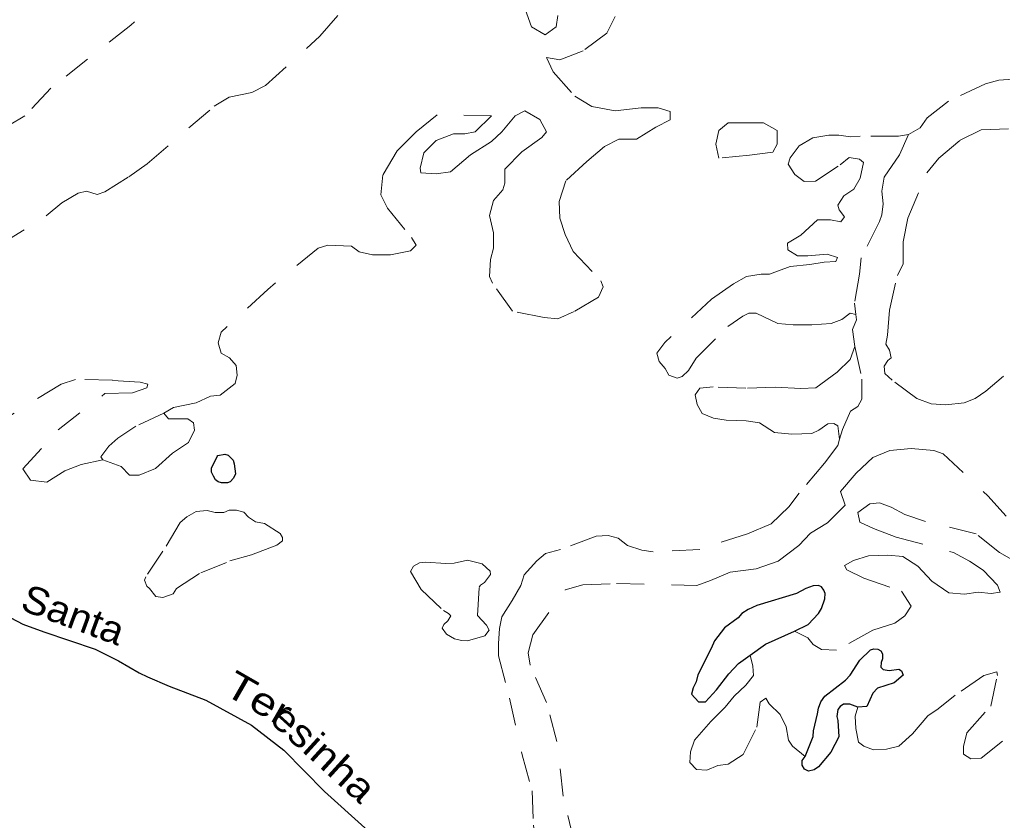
# Model space of a CAD drawing. Extents: x 344.9 to 371, y 7566.4 to 7594.3.
# Drawn here: x 362.086 to 365.656, y 7583.086 to 7585.996 of the extents above; entities that cross this region are included whole.
import ezdxf
from ezdxf.enums import TextEntityAlignment as Align

# ---------------------------------------------------------------- set-up
doc = ezdxf.new("R2010")
doc.units = 0
doc.header["$LTSCALE"] = 0.04
doc.linetypes.add('SHORT_DASHED', pattern=[2.7, 1.5, -1.2])
for name, color, linetype, lineweight in [('17', 7, 'SHORT_DASHED', 13), ('2', 7, 'Continuous', 25), ('21', 7, 'SHORT_DASHED', 13), ('7', 7, 'Continuous', 25)]:
    doc.layers.add(name, color=color, linetype=linetype, lineweight=lineweight)
doc.layers.add('61', color=7, linetype='Continuous')

msp = doc.modelspace()

# ---------------------------------------------------------------- linework, layer by layer
at = {"layer": '17'}
for points in [[(365.3151, 7585.5786), (365.282, 7585.5043), (365.227, 7585.4229), (365.2182, 7585.3723), (365.2226, 7585.3261), (365.2182, 7585.2865), (365.2094, 7585.2623), (365.1434, 7585.1303), (365.1368, 7585.0709), (365.1192, 7584.9653), (365.123, 7584.9245)], [(365.12, 7584.8076), (365.1456, 7584.6893), (365.1456, 7584.6167), (365.1302, 7584.5903), (365.1038, 7584.5727), (365.0752, 7584.5067), (365.0637, 7584.4714)], [(362.6098, 7584.5657), (362.5082, 7584.5184), (362.4428, 7584.4748), (362.4096, 7584.4454), (362.3802, 7584.4065), (362.3884, 7584.3962)]]:
    msp.add_lwpolyline(points, dxfattribs=at)
at = {"layer": '2'}
msp.add_lwpolyline([(362.8031, 7584.4079), (362.8063, 7584.4118), (362.8309, 7584.4166), (362.8428, 7584.4126), (362.8611, 7584.3952), (362.8656, 7584.382), (362.8698, 7584.3452), (362.8627, 7584.3293), (362.85, 7584.3158), (362.841, 7584.3126), (362.819, 7584.3121), (362.8065, 7584.3163), (362.7968, 7584.3237), (362.7894, 7584.3362), (362.7832, 7584.3507), (362.7824, 7584.3658)], close=True, dxfattribs=at)
for points in [[(364.9008, 7583.774), (364.9507, 7583.7976), (364.9882, 7583.8379), (364.9989, 7583.856), (365.0104, 7583.8908), (365.0118, 7583.9098), (365.0076, 7583.9223), (364.9988, 7583.9343), (364.9881, 7583.939), (364.9682, 7583.938), (364.9418, 7583.9283), (364.9076, 7583.9102), (364.764, 7583.8668), (364.7325, 7583.8524), (364.7089, 7583.8371), (364.6955, 7583.8222), (364.6462, 7583.7861), (364.6096, 7583.7385), (364.5985, 7583.7099), (364.5493, 7583.6146), (364.5437, 7583.5892), (364.5326, 7583.567), (364.5271, 7583.5447), (364.5517, 7583.5169), (364.5779, 7583.5169), (364.6168, 7583.5606), (364.6621, 7583.6185), (364.6978, 7583.6559), (364.7391, 7583.686)], [(364.7391, 7583.686), (364.7955, 7583.7257), (364.9008, 7583.774)], [(365.1385, 7583.6686), (365.1774, 7583.7059), (365.1894, 7583.7091), (365.2037, 7583.7083), (365.2139, 7583.7019), (365.2203, 7583.6916), (365.2203, 7583.6734), (365.2155, 7583.6591), (365.2147, 7583.6432), (365.2227, 7583.6336), (365.2449, 7583.6304), (365.2799, 7583.6352), (365.2894, 7583.6297), (365.2957, 7583.613), (365.2632, 7583.5852), (365.2021, 7583.5661), (365.1854, 7583.5487), (365.1631, 7583.4994), (365.1314, 7583.4978)], [(364.9844, 7583.4733), (364.9876, 7583.4939), (364.9964, 7583.5161), (365.0115, 7583.5368), (365.0861, 7583.5955), (365.1028, 7583.613), (365.1385, 7583.6686)], [(365.1314, 7583.4978), (365.102, 7583.5082), (365.079, 7583.5082), (365.0663, 7583.5002), (365.0583, 7583.4891), (365.0543, 7583.4637), (365.0583, 7583.4486), (365.0623, 7583.3899), (365.0329, 7583.3335), (364.9884, 7583.2803), (364.9718, 7583.2691), (364.9511, 7583.2652), (364.9368, 7583.2715), (364.9289, 7583.2866), (364.9289, 7583.3033), (364.94, 7583.3176)], [(364.94, 7583.3176), (364.9686, 7583.3907), (364.9701, 7583.4113), (364.9844, 7583.4733)]]:
    msp.add_lwpolyline(points, dxfattribs=at)
at = {"layer": '21'}
for points in [[(363.0764, 7586.6295), (363.067, 7586.6106), (363.067, 7586.5349), (363.0409, 7586.4829), (362.9771, 7586.4167), (362.944, 7586.3765), (362.7878, 7586.2629), (362.6553, 7586.1174), (362.4898, 7585.9755), (362.1988, 7585.7461), (362.1042, 7585.6456), (362.0474, 7585.6125)], [(362.0168, 7585.1797), (362.1824, 7585.2826), (362.2392, 7585.3299), (362.2983, 7585.3654), (362.329, 7585.3725), (362.3669, 7585.3606), (362.3953, 7585.3701), (362.4828, 7585.4245), (362.549, 7585.4718), (362.7926, 7585.6811), (362.847, 7585.7142), (362.9298, 7585.7308), (362.9795, 7585.7568), (363.1758, 7585.9354), (363.2846, 7586.0607)], [(363.916, 7586.0512), (363.9457, 7585.9701), (363.9944, 7585.9403), (364.035, 7585.9701), (364.0404, 7586.0106)], [(364.2487, 7586.0066), (364.219, 7585.9471), (364.1324, 7585.8822), (364.0485, 7585.8497), (363.9998, 7585.8578), (364.0242, 7585.8064), (364.1026, 7585.7171), (364.1648, 7585.6806), (364.2487, 7585.6644), (364.3434, 7585.6752), (364.4056, 7585.6752), (364.4489, 7585.6617), (364.4489, 7585.6319), (364.3975, 7585.6049), (364.3272, 7585.5616), (364.2622, 7585.5616), (364.2108, 7585.5345), (364.1459, 7585.4804), (364.0701, 7585.4101), (364.0458, 7585.3343), (364.0485, 7585.2748), (364.0674, 7585.2153), (364.0972, 7585.1531), (364.1973, 7585.0463), (364.2054, 7585.0247), (364.1892, 7584.9868), (364.0999, 7584.9354), (364.0404, 7584.9083), (363.9917, 7584.9138), (363.8758, 7584.9358), (363.8032, 7585.0378), (363.7928, 7585.062), (363.7962, 7585.1243), (363.8066, 7585.1658), (363.8066, 7585.2211), (363.7928, 7585.2834), (363.8066, 7585.3387), (363.8412, 7585.3768), (363.8481, 7585.401), (363.8481, 7585.4529), (363.9104, 7585.5151), (363.983, 7585.567), (364.0003, 7585.5878), (363.9761, 7585.6327), (363.9208, 7585.6639), (363.8862, 7585.6466), (363.8378, 7585.5878), (363.7997, 7585.5532), (363.7236, 7585.5048), (363.651, 7585.4425), (363.5991, 7585.4356), (363.5437, 7585.439), (363.5403, 7585.4563), (363.5541, 7585.5117), (363.5991, 7585.5566), (363.6613, 7585.5809), (363.7029, 7585.5809), (363.7409, 7585.5878), (363.7997, 7585.6466), (363.6025, 7585.65), (363.5265, 7585.5878), (363.4573, 7585.5186), (363.4054, 7585.4321), (363.3985, 7585.3595), (363.4227, 7585.3111), (363.5092, 7585.2039), (363.5265, 7585.1762), (363.5057, 7585.1554), (363.4331, 7585.1416), (363.3673, 7585.1416)], [(365.6937, 7585.7789), (365.6436, 7585.7759), (365.595, 7585.7622), (365.4599, 7585.6999), (365.3825, 7585.6392), (365.3576, 7585.6029), (365.3151, 7585.5786)], [(365.6605, 7584.6997), (365.5956, 7584.6453), (365.5574, 7584.6185), (365.5173, 7584.6033), (365.4504, 7584.5956), (365.397, 7584.5994), (365.3454, 7584.6185), (365.2556, 7584.6854), (365.2289, 7584.7102), (365.227, 7584.7369), (365.2401, 7584.7566), (365.2518, 7584.7665), (365.246, 7584.7952), (365.2327, 7584.8162), (365.2384, 7584.8487), (365.246, 7584.9403), (365.2747, 7585.0664), (365.2957, 7585.1084), (365.2957, 7585.1886), (365.3129, 7585.2746), (365.3817, 7585.4388), (365.4256, 7585.4923), (365.502, 7585.5572), (365.5784, 7585.5954), (365.6777, 7585.5993)], [(365.3151, 7585.5786), (365.2786, 7585.5726), (365.139, 7585.5726), (365.104, 7585.5695), (365.0615, 7585.5756), (365.0251, 7585.5756), (364.9674, 7585.5665), (364.9173, 7585.5376), (364.8854, 7585.4936), (364.8778, 7585.4708), (364.9021, 7585.4329), (364.9355, 7585.4071), (364.9765, 7585.4086), (365.0661, 7585.4678), (365.0995, 7585.4951), (365.1374, 7585.4891), (365.1511, 7585.4769), (365.139, 7585.4192), (365.1162, 7585.3798), (365.0798, 7585.3555), (365.0585, 7585.3213)], [(365.0585, 7585.3213), (365.063, 7585.3046), (365.0828, 7585.2788), (365.0691, 7585.2606), (365.0311, 7585.2682), (364.9841, 7585.2682), (364.9233, 7585.212), (364.8748, 7585.1831), (364.8763, 7585.1589), (364.9112, 7585.1376), (364.9492, 7585.1376), (365.019, 7585.1437), (365.0569, 7585.1315), (365.0509, 7585.1163), (365.0084, 7585.1148), (364.9567, 7585.1057), (364.8847, 7585.0984), (364.8103, 7585.0711), (364.7799, 7585.0711), (364.7268, 7585.062), (364.6797, 7585.0362), (364.5993, 7584.98), (364.4292, 7584.8221), (364.4004, 7584.7842), (364.4095, 7584.7538), (364.4307, 7584.728), (364.4444, 7584.7037), (364.4748, 7584.6931), (364.493, 7584.6991), (364.5158, 7584.7204), (364.5431, 7584.7659), (364.6585, 7584.8805), (364.7131, 7584.9185), (364.7344, 7584.9291), (364.7617, 7584.9291), (364.8406, 7584.8911), (364.8953, 7584.8866), (364.9636, 7584.8866), (365.0335, 7584.8911), (365.0729, 7584.9063), (365.1033, 7584.9291), (365.123, 7584.9245)], [(363.2048, 7585.1762), (363.1702, 7585.1658), (362.9868, 7585.0153), (362.8174, 7584.8597), (362.807, 7584.8216), (362.8174, 7584.7836), (362.8485, 7584.7663), (362.8727, 7584.7386), (362.8762, 7584.704), (362.8692, 7584.6729), (362.8139, 7584.6314), (362.7793, 7584.6279), (362.7274, 7584.6037), (362.6444, 7584.5864), (362.6098, 7584.5657)], [(363.3673, 7585.1416), (363.3189, 7585.152), (363.2912, 7585.1727), (363.2048, 7585.1762)], [(365.123, 7584.9245), (365.1261, 7584.9048), (365.1109, 7584.8699), (365.12, 7584.8076)], [(365.12, 7584.8076), (365.1033, 7584.7606), (365.0562, 7584.715), (364.9788, 7584.6581), (364.9241, 7584.6551), (364.83, 7584.6596), (364.7237, 7584.6566), (364.6053, 7584.6611), (364.5567, 7584.6566), (364.54, 7584.6323), (364.5476, 7584.5974), (364.5658, 7584.564), (364.6068, 7584.5473), (364.6524, 7584.5397), (364.7253, 7584.5382), (364.7738, 7584.5306), (364.8285, 7584.4957), (364.8908, 7584.4888), (364.9636, 7584.4919), (364.9894, 7584.504), (365.0213, 7584.5268), (365.0441, 7584.5283), (365.0578, 7584.5192), (365.0637, 7584.4714)], [(362.3884, 7584.3962), (362.3089, 7584.3789), (362.2501, 7584.3564), (362.1844, 7584.3149), (362.1256, 7584.3218), (362.0979, 7584.3633), (362.2259, 7584.5051), (362.3954, 7584.6366), (362.4957, 7584.64), (362.5476, 7584.6573), (362.551, 7584.6712), (362.5234, 7584.6781), (362.423, 7584.685), (362.2881, 7584.6885), (362.2363, 7584.6712), (361.9293, 7584.4819)], [(362.6098, 7584.5657), (362.6271, 7584.5449), (362.6963, 7584.5449), (362.717, 7584.5311), (362.7205, 7584.5034), (362.6997, 7584.4585), (362.6409, 7584.4204), (362.5787, 7584.3651), (362.5199, 7584.3409), (362.4853, 7584.3409), (362.4542, 7584.372), (362.3884, 7584.3962)], [(365.0637, 7584.4714), (365.0577, 7584.4486), (365.0091, 7584.3834), (364.918, 7584.2748), (364.8801, 7584.2247), (364.8163, 7584.164), (364.7298, 7584.1275), (364.5567, 7584.0706), (364.3867, 7584.0615), (364.3457, 7584.0675), (364.2941, 7584.0842), (364.2607, 7584.1116), (364.2242, 7584.1207), (364.1802, 7584.1192), (364.0512, 7584.0698), (363.9965, 7584.0561), (363.9646, 7584.0288), (363.9191, 7583.9787), (363.9069, 7583.9392), (363.875, 7583.8846)], [(364.1008, 7583.0057), (364.0607, 7583.1744), (364.0371, 7583.3724), (363.9994, 7583.5139), (363.9405, 7583.6496), (363.9334, 7583.6944), (363.9499, 7583.7604), (364.0678, 7583.9231), (364.1315, 7583.942), (364.2541, 7583.9467), (364.5465, 7583.9396), (364.596, 7583.9573), (364.6668, 7583.988), (364.7611, 7583.9998), (364.8413, 7584.0281), (364.9167, 7584.0847), (364.9592, 7584.1295), (365.0205, 7584.1672), (365.0842, 7584.2309), (365.0677, 7584.2816), (365.1243, 7584.3477), (365.1856, 7584.4043), (365.2469, 7584.4302), (365.3247, 7584.4373), (365.4073, 7584.4302), (365.4403, 7584.4184), (365.603, 7584.2651), (365.6808, 7584.1791)], [(365.7209, 7584.0164), (365.6454, 7584.0588), (365.5606, 7584.1272), (365.3766, 7584.172), (365.3012, 7584.1979), (365.2516, 7584.2239), (365.2092, 7584.2404), (365.1738, 7584.2357), (365.1314, 7584.205), (365.1384, 7584.1696), (365.188, 7584.1461), (365.2705, 7584.1154), (365.478, 7584.0588), (365.537, 7584.0282), (365.5865, 7583.9952), (365.6384, 7583.9409), (365.6478, 7583.915), (365.6148, 7583.9103), (365.5676, 7583.915), (365.5181, 7583.9079), (365.4615, 7583.9126), (365.4002, 7583.9551), (365.3483, 7584.0093), (365.2941, 7584.0447), (365.2398, 7584.0494), (365.1691, 7584.047), (365.1149, 7584.0305), (365.0818, 7584.0117), (365.0912, 7583.9964), (365.1525, 7583.9658), (365.2893, 7583.9186), (365.3247, 7583.8644), (365.3011, 7583.829), (365.2657, 7583.8031), (365.1856, 7583.7771), (365.0535, 7583.704), (364.9993, 7583.7064), (364.9686, 7583.7252), (364.9497, 7583.7488), (364.9008, 7583.774)], [(363.875, 7583.8846), (363.8371, 7583.8254), (363.8295, 7583.7836), (363.8249, 7583.7289), (363.8249, 7583.6833), (363.8659, 7583.53), (363.9114, 7583.3235), (363.9479, 7583.193), (363.9524, 7583.0685), (363.96, 7583.0048), (363.9691, 7582.9623), (363.9615, 7582.9273), (363.9615, 7582.9015), (363.9751, 7582.8621), (363.9796, 7582.5851)], [(364.7391, 7583.686), (364.7497, 7583.6457), (364.752, 7583.6127), (364.7238, 7583.5773), (364.6813, 7583.5372), (364.6483, 7583.4971), (364.5964, 7583.4453), (364.5375, 7583.3769), (364.5233, 7583.3344), (364.5209, 7583.2967), (364.5445, 7583.2708), (364.5823, 7583.2684), (364.6223, 7583.2849), (364.6601, 7583.2896), (364.7143, 7583.325), (364.7638, 7583.424), (364.7756, 7583.516), (364.7969, 7583.5302), (364.8086, 7583.5089), (364.8487, 7583.4712), (364.87, 7583.4264), (364.8794, 7583.3769), (364.8935, 7583.3557), (364.94, 7583.3176)], [(365.6566, 7583.3737), (365.5788, 7583.3124), (365.5411, 7583.3101), (365.5152, 7583.3266), (365.5152, 7583.3549), (365.5269, 7583.4044), (365.6142, 7583.5011), (365.6378, 7583.6119), (365.6354, 7583.626), (365.5883, 7583.6119), (365.4845, 7583.5411), (365.4232, 7583.4916), (365.3855, 7583.4657), (365.3289, 7583.4009), (365.2794, 7583.3561), (365.2346, 7583.3443), (365.1874, 7583.342), (365.152, 7583.3561), (365.1332, 7583.3702), (365.1237, 7583.4198), (365.1214, 7583.4646), (365.1314, 7583.4978)]]:
    msp.add_lwpolyline(points, dxfattribs=at)
for points in [[(364.6261, 7585.4923), (364.615, 7585.5427), (364.6261, 7585.5931), (364.6596, 7585.6211), (364.7155, 7585.6211), (364.7881, 7585.6211), (364.8383, 7585.5931), (364.8383, 7585.5427), (364.8216, 7585.5147), (364.7378, 7585.5035)], [(362.9421, 7584.1705), (362.9166, 7584.188), (362.8999, 7584.206), (362.8734, 7584.213), (362.847, 7584.213), (362.8275, 7584.2046), (362.7956, 7584.2046), (362.7664, 7584.2116), (362.7274, 7584.2088), (362.6926, 7584.1893), (362.669, 7584.1685), (362.6064, 7584.0642), (362.5438, 7583.971), (362.5397, 7583.9592), (362.548, 7583.9369), (362.5578, 7583.9286), (362.58, 7583.8994), (362.6064, 7583.8952), (362.644, 7583.9091), (362.6551, 7583.9286), (362.7441, 7583.9856), (362.8498, 7584.0287), (362.9278, 7584.0503), (363.0196, 7584.0865), (363.0404, 7584.1018), (363.0404, 7584.1143), (363.0321, 7584.1282), (362.9751, 7584.1643)], [(363.7485, 7583.8306), (363.755, 7583.9329), (363.7601, 7583.9404), (363.7749, 7583.9503), (363.7963, 7583.979), (363.7954, 7583.9913), (363.7659, 7584.0184), (363.7125, 7584.0316), (363.664, 7584.0209), (363.6345, 7584.0193), (363.5605, 7584.0242), (363.5384, 7584.0217), (363.517, 7584.0102), (363.5055, 7583.9897), (363.5449, 7583.9248), (363.6254, 7583.8484), (363.6437, 7583.8382), (363.6525, 7583.8295), (363.641, 7583.8107), (363.6263, 7583.7975), (363.6213, 7583.7844), (363.6369, 7583.7622), (363.6657, 7583.7458), (363.6911, 7583.7392), (363.7133, 7583.7384), (363.7757, 7583.7565), (363.7913, 7583.777), (363.7823, 7583.7951)]]:
    msp.add_lwpolyline(points, close=True, dxfattribs=at)
at = {"layer": '7'}
for points in [[(361.459, 7584.1943), (361.5672, 7584.1213), (361.6541, 7584.068), (361.7307, 7584.0313), (361.8151, 7583.9715), (361.8608, 7583.932), (361.9452, 7583.8788), (362.0975, 7583.7994), (362.1736, 7583.7715)], [(362.1736, 7583.7715), (362.3604, 7583.708), (362.4448, 7583.6662), (362.52, 7583.6217), (362.55, 7583.6073), (362.6289, 7583.5734), (362.7627, 7583.5226), (362.9279, 7583.4317), (363.046, 7583.3408), (363.1931, 7583.1914), (363.3393, 7583.0583), (363.7767, 7582.6929), (363.8487, 7582.6465), (363.9796, 7582.5851)]]:
    msp.add_lwpolyline(points, dxfattribs=at)

# ---------------------------------------------------------------- texts
at = {"layer": '61'}
for s, rotation, width, p in [('Santa', 339.766, 1.1, (362.2633, 7583.7865)), ('Ter', 330.068, 1.25, (362.9305, 7583.4854)), ('esinha', 317.763, 1.15, (363.156, 7583.2949))]:
    msp.add_text(s, height=0.1, rotation=rotation, dxfattribs=dict(at, width=width)).set_placement(p, align=Align.CENTER)

doc.saveas('drawing.dxf')
